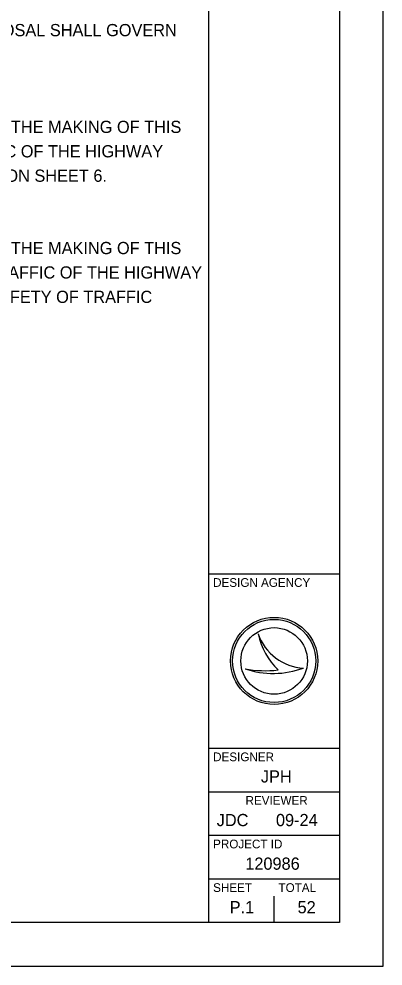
# Model space of a CAD drawing. Extents: x 0 to 34, y 0 to 22.
# Drawn here: x 29.82 to 34, y 0 to 10.86 of the extents above; entities that cross this region are included whole.
import ezdxf

# ---------------------------------------------------------------- set-up
doc = ezdxf.new("R2010")
doc.units = 0
for name, color, linetype in [('SH_Border', 7, 'Continuous'), ('SH_Cut_Line', 7, 'Continuous'), ('SH_Data', 7, 'Continuous'), ('SH_Text', 7, 'Continuous')]:
    doc.layers.add(name, color=color, linetype=linetype)

msp = doc.modelspace()

# ---------------------------------------------------------------- linework, layer by layer
at = {"layer": 'SH_Border'}
for p, q in [((32, 0.5), (32, 21.5)), ((32, 4.5), (33.5, 4.5)), ((32, 2.5), (33.5, 2.5)), ((32, 2), (33.5, 2)), ((32, 1.5), (33.5, 1.5)), ((32, 1), (33.5, 1))]:
    msp.add_line(p, q, dxfattribs=at)
msp.add_lwpolyline([(1.5, 21.5), (33.5, 21.5), (33.5, 0.5), (1.5, 0.5)], close=True, dxfattribs=at)
at = {"layer": 'SH_Cut_Line'}
msp.add_lwpolyline([(0, 0), (34, 0), (34, 22), (0, 22)], close=True, dxfattribs=at)
at = {"layer": 'SH_Data'}
for p, q in [((32.567, 3.81), (32.567, 3.81)), ((32.75, 3.5), (32.75, 3.5)), ((32.417, 3.41), (32.417, 3.41)), ((33.087, 3.419), (33.087, 3.419)), ((32.75, 0.5), (32.75, 0.8)), ((32.375, 0.675), (32.375, 0.675))]:
    msp.add_line(p, q, dxfattribs=at)
for radius in [0.5, 0.477, 0.477, 0.382]:
    msp.add_circle((32.75, 3.5), radius, dxfattribs=at)
for centre, radius, start, end in [((33.116, 3.998), 0.58, 198.9257, 198.9319), ((33.347, 3.97), 0.796, 191.6379, 191.6421), ((33.116, 3.998), 0.58, 198.9319, 267.1657), ((33.347, 3.97), 0.796, 191.6421, 226.0947), ((32.739, 4.37), 1.013, 251.4576, 290.0832), ((32.648, 4.654), 1.266, 259.4964, 259.4995), ((32.739, 4.37), 1.013, 251.4527, 251.4576), ((32.648, 4.654), 1.266, 259.4995, 276.6672)]:
    msp.add_arc(centre, radius, start, end, dxfattribs=at)

# ---------------------------------------------------------------- texts
for s, height, p in [(' I HEREBY APPROVE THESE PLANS AND DECLARE THAT THE MAKING OF THIS', 0.14, (24.528, 9.557)), ('IMPROVEMENT WILL REQUIRE THE CLOSING TO TRAFFIC OF THE HIGHWAY', 0.14, (24.528, 9.277)), ('AND THAT DETOURS WILL BE PROVIDED AS INDICATED ON SHEET 6.', 0.14, (24.528, 8.997)), (' I HEREBY APPROVE THESE PLANS AND DECLARE THAT THE MAKING OF THIS', 0.14, (24.528, 8.167)), ('IMPROVEMENT WILL NOT REQUIRE THE CLOSING TO TRAFFIC OF THE HIGHWAY', 0.14, (24.528, 7.887)), ('AND THAT PROVISIONS FOR THE MAINTENANCE AND SAFETY OF TRAFFIC', 0.14, (24.528, 7.607)), ('DESIGN AGENCY', 0.1, (32.05, 4.35)), ('DESIGNER', 0.1, (32.05, 2.35)), ('JPH', 0.14, (32.598, 2.105)), ('REVIEWER', 0.1, (32.422, 1.85)), ('JDC', 0.14, (32.091, 1.605)), ('09-24', 0.14, (32.771, 1.605)), ('PROJECT ID', 0.1, (32.05, 1.35)), ('120986', 0.14, (32.419, 1.105)), ('SHEET', 0.1, (32.05, 0.85)), ('TOTAL', 0.1, (32.8, 0.85)), ('P.1', 0.14, (32.24, 0.605)), ('52', 0.14, (33.019, 0.605))]:
    msp.add_text(s, height=height, dxfattribs=at).set_placement(p)
at = {"layer": 'SH_Text'}
msp.add_text('SPECIFICATION 800 VERSION INDICATED ON THE PROPOSAL SHALL GOVERN', height=0.14, dxfattribs=at).set_placement((24.528, 10.667))

doc.saveas('drawing.dxf')
